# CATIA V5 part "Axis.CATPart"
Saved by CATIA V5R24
Part number: Axis
Bounding box of the stored display mesh (mm): x -8.5 to 8.5, y -21.55 to -20.45, z 0.85 to 1.95
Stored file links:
  C:\Users\Jules\Documents\ECL\Watch\Axis.CATPart
  C:\Users\Jules\Documents\ECL\Watch\Side link.CATPart
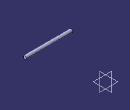
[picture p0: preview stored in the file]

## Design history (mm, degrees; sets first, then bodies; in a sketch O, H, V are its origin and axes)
Body1 (main body)
  DatumSurface1
  Sketch1 on yz-plane, origin (0, 0, 0), H (0, 1, 0), V (0, 0, 1)
    construction line L1 (-24, 2.8) -> (-21, 2.8)
    construction arc A1 centre (-21, 1.4) radius 1.4 from (-21, 2.8) to (-21, 0) cw
    point P3 (-21, 1.4)
    point P4 (-21, 0)
    construction line L2 (-21, 0) -> (-24, 0)
    construction arc A2 centre (-24, 1.4) radius 1.4 from (-24, 0) to (-24, 2.8) cw
    circle A3 centre (-21, 1.4) radius 0.55
    construction circle A4 centre (-24, 1.4) radius 0.55
    radius A1 = 1.4
    length L2 = 3
    distance P3 V = 21
    radius A3 = 0.55
    radius A4 = 0.55
    horizontal: L1 H
    coincidence: P4 H
    tangency: A1 L1, L2 A1, A2 L1, A2 L2
  Pad1: profile Sketch1, direction (1, 0, 0), length 8.5, mirrored extent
